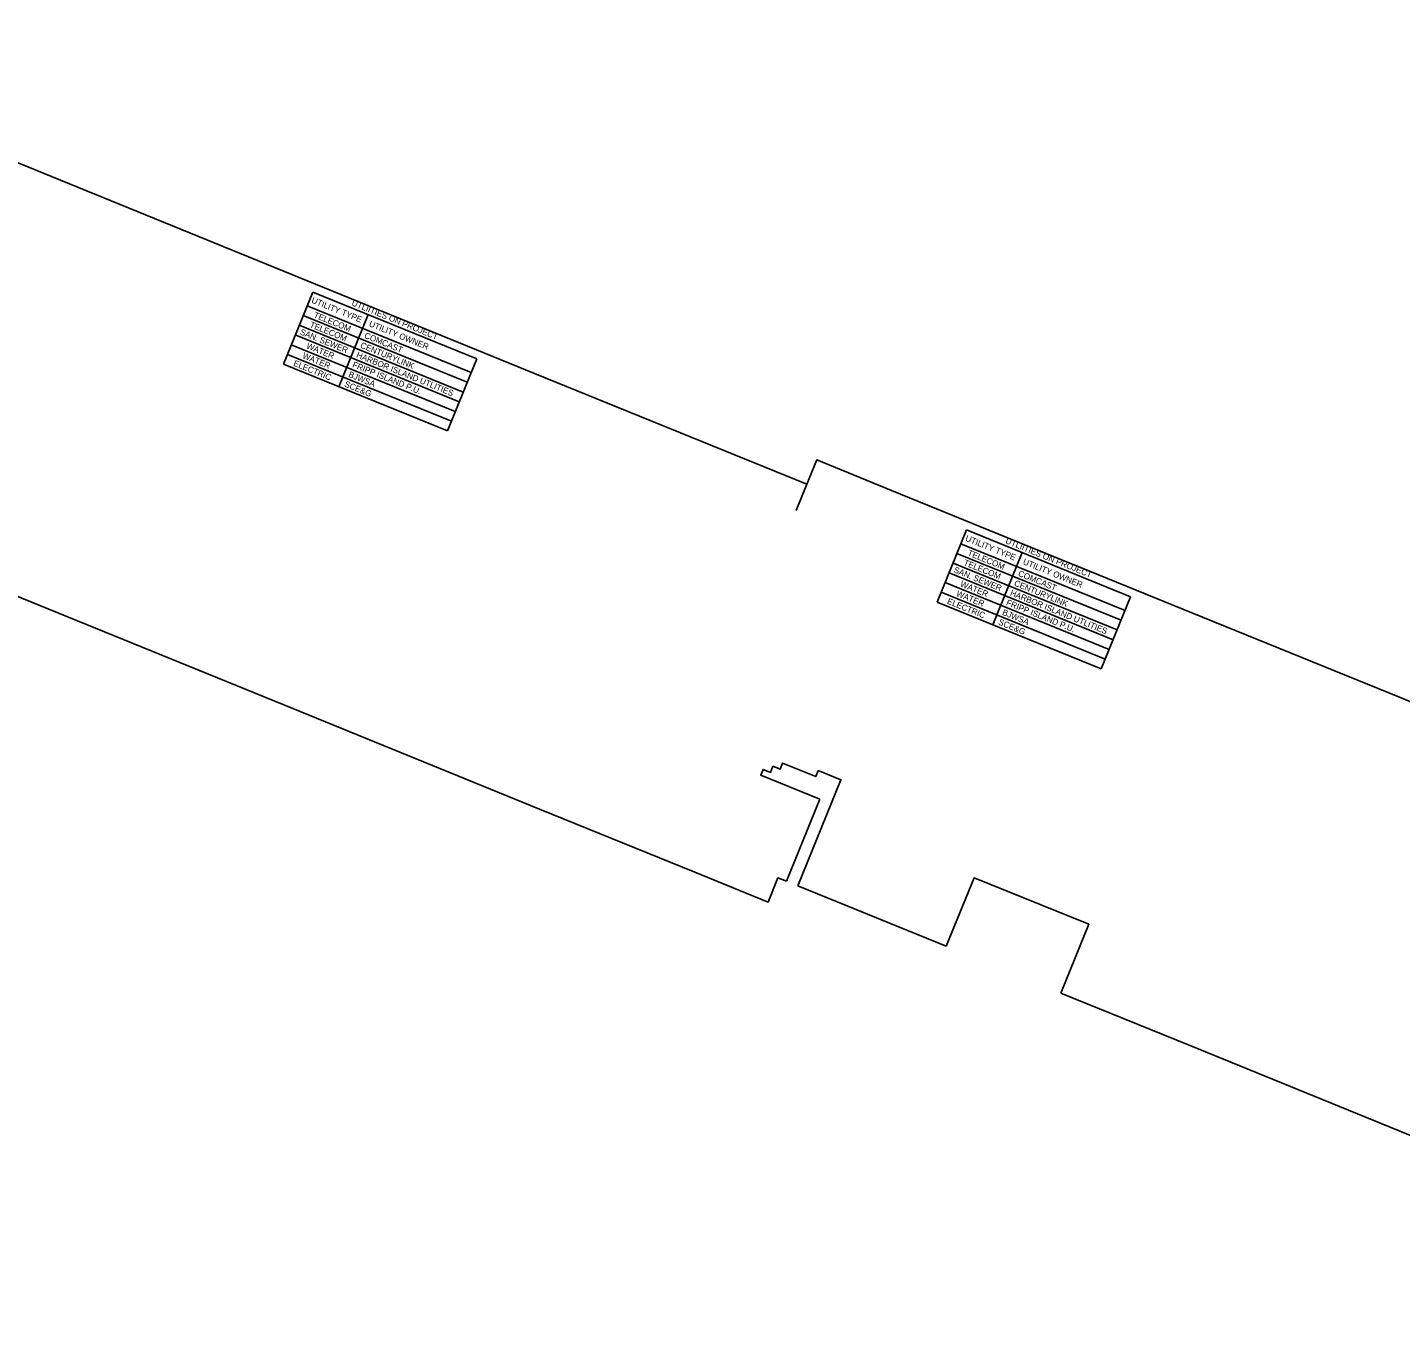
# Model space of a CAD drawing. Extents: x 2162629 to 2176228, y 202467 to 210920.
# Drawn here: x 2166029 to 2167729, y 208196 to 209814 of the extents above; entities that cross this region are included whole.
import ezdxf

# ---------------------------------------------------------------- set-up
doc = ezdxf.new("R2010")
doc.units = 0
doc.layers.add('RD_SHT_ShtClip', color=7, linetype='Continuous')
doc.layers.add('RD_SHT_TX', color=7, linetype='Continuous')

msp = doc.modelspace()

# ---------------------------------------------------------------- linework, layer by layer
at = {"layer": 'RD_SHT_ShtClip'}
for p, q in [((2166968.3, 208757.4), (2167009.7, 208859)), ((2166957.8, 208761.7), (2166968.3, 208757.4)), ((2166982.2, 208751.7), (2167166.2, 208676.8))]:
    msp.add_line(p, q, dxfattribs=at)
for points in [[(2166980.2, 209216.5), (2166980.2, 209216.5), (2166993.4, 209248.9), (2166656.3, 209386.2), (2166313.3, 209525.9), (2166069.4, 209625.3), (2165896.3, 209695.8), (2165697.6, 209776.7), (2165605, 209814.4), (2165595.5, 209791.3), (2165594.4, 209788.6)], [(2165574.9, 209289.8), (2165769.1, 209210.7), (2166066.1, 209089.8), (2166346.2, 208975.7), (2166662.5, 208846.8), (2166854.9, 208768.5), (2166945.5, 208731.6), (2166957.8, 208761.7)], [(2168393.4, 208713.8), (2168057, 208850.8), (2167714, 208990.5), (2167470.1, 209089.8), (2167297, 209160.3), (2167098.3, 209241.3), (2167005.7, 209279), (2166996.2, 209255.9), (2166980.2, 209216.5)], [(2167009.7, 208859), (2166936.5, 208888.8), (2166939.3, 208895.9), (2166948.4, 208892.2), (2166951.5, 208899.7), (2166960.3, 208896.1), (2166963.4, 208903.6), (2167004.5, 208886.9), (2167007.6, 208894.4), (2167035.7, 208883), (2166982.2, 208751.7)], [(2167166.2, 208676.8), (2167200.8, 208761.8), (2167342.6, 208704.1), (2167307.9, 208619)], [(2167307.9, 208619), (2167466.8, 208554.3), (2167746.9, 208440.2), (2168063.2, 208311.4), (2168255.6, 208233), (2168346.2, 208196.1), (2168361.8, 208234.4)]]:
    msp.add_lwpolyline(points, dxfattribs=at)
at = {"layer": 'RD_SHT_TX'}
for p, q in [((2166381.9, 209486.9), (2166345.5, 209397.6)), ((2166381.9, 209486.9), (2166584.9, 209404.2)), ((2166374.9, 209469.8), (2166577.9, 209387.1)), ((2166450.6, 209458.9), (2166414.2, 209369.6)), ((2166365.1, 209445.8), (2166568.1, 209363.1)), ((2166370, 209457.8), (2166573, 209375.1)), ((2166360.2, 209433.7), (2166563.2, 209351)), ((2166350.4, 209409.7), (2166553.4, 209327)), ((2166355.3, 209421.7), (2166558.3, 209339)), ((2166345.5, 209397.6), (2166548.5, 209315)), ((2166584.9, 209404.2), (2166548.5, 209315)), ((2167191.3, 209192.3), (2167154.9, 209103)), ((2167191.3, 209192.3), (2167394.3, 209109.6)), ((2167184.3, 209175.2), (2167387.4, 209092.5)), ((2167179.4, 209163.2), (2167382.5, 209080.5)), ((2167260.1, 209164.3), (2167223.7, 209075)), ((2167169.6, 209139.1), (2167372.7, 209056.4)), ((2167174.5, 209151.2), (2167377.6, 209068.5)), ((2167164.7, 209127.1), (2167367.8, 209044.4)), ((2167154.9, 209103), (2167358, 209020.3)), ((2167159.8, 209115.1), (2167362.9, 209032.4)), ((2167394.3, 209109.6), (2167358, 209020.3))]:
    msp.add_line(p, q, dxfattribs=at)

# ---------------------------------------------------------------- texts
for s, p in [('UTILITY TYPE', (2166379.5, 209473.9)), ('UTLIITIES ON PROJECT', (2166429.2, 209470.6)), ('TELECOM', (2166382.3, 209455.7)), ('TELECOM', (2166377.4, 209443.7)), ('UTILITY OWNER', (2166450.8, 209444.8)), ('SAN. SEWER', (2166365.2, 209434.7)), ('COMCAST', (2166444.9, 209430.3)), ('WATER', (2166368.3, 209405.3)), ('WATER', (2166373.2, 209417.4)), ('HARBOR ISLAND UTLITIES', (2166435.1, 209406.2)), ('CENTURYLINK', (2166440, 209418.2)), ('ELECTRIC', (2166357.1, 209395.9)), ('FRIPP ISLAND P.U.', (2166430.2, 209394.2)), ('SCE&G', (2166420.4, 209370.1)), ('BJWSA', (2166425.3, 209382.1)), ('UTILITY TYPE', (2167189, 209179.3)), ('UTLIITIES ON PROJECT', (2167238.7, 209176)), ('TELECOM', (2167186.9, 209149.1)), ('TELECOM', (2167191.8, 209161.1)), ('UTILITY OWNER', (2167260.3, 209150.2)), ('SAN. SEWER', (2167174.6, 209140.1)), ('COMCAST', (2167254.3, 209135.6)), ('WATER', (2167182.7, 209122.7)), ('CENTURYLINK', (2167249.4, 209123.6)), ('ELECTRIC', (2167166.5, 209101.3)), ('WATER', (2167177.8, 209110.7)), ('FRIPP ISLAND P.U.', (2167239.6, 209099.6)), ('HARBOR ISLAND UTLITIES', (2167244.5, 209111.6)), ('BJWSA', (2167234.7, 209087.5)), ('SCE&G', (2167229.8, 209075.5))]:
    msp.add_text(s, height=7.5, rotation=337.8388, dxfattribs=at).set_placement(p)

doc.saveas('drawing.dxf')
